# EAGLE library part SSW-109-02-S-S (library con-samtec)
THROUGH-HOLE .025" SQ POST SOCKET Source: Samtec SSW.pdf
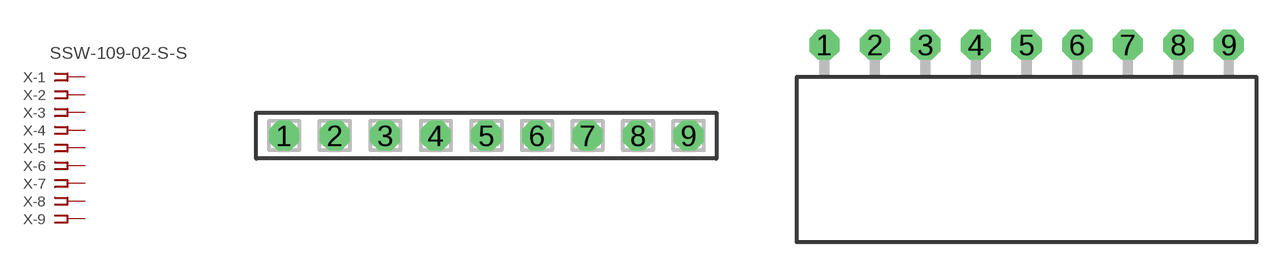
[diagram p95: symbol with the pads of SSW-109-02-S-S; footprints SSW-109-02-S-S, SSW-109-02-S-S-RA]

Designator prefix X; gates -1=FPINV -2=FPIN -3=FPIN -4=FPIN -5=FPIN -6=FPIN -7=FPIN -8=FPIN -9=FPIN

## SSW-109-02-S-S (MPN: SSW-109-02-S-S; OC_FARNELL: unknown; OC_NEWARK: 11P9465)  [SSW-109-02-S-S]
1  -1:1  pas
2  -2:1  pas
3  -3:1  pas
4  -4:1  pas
5  -5:1  pas
6  -6:1  pas
7  -7:1  pas
8  -8:1  pas
9  -9:1  pas

## SSW-109-02-S-S-RA (MPN: SSW-109-02-S-S-RA; OC_FARNELL: unknown; OC_NEWARK: 11P9466)  [SSW-109-02-S-S-RA]
Pads as for SSW-109-02-S-S

## Footprint SSW-109-02-S-S (pad centres in mm)
THROUGH-HOLE .025" SQ POST SOCKET Source: Samtec SSW.pdf
drill 1 pad 1.5 octagon: 1 -10.16,0; 2 -7.62,0; 3 -5.08,0; 4 -2.54,0; 5 0,0; 6 2.54,0; 7 5.08,0; 8 7.62,0; 9 10.16,0

## Footprint SSW-109-02-S-S-RA (pad centres in mm)
THROUGH-HOLE .025" SQ POST SOCKET Source: Samtec SSW.pdf
drill 1 pad 1.5 octagon: 1 -10.16,1.524; 2 -7.62,1.524; 3 -5.08,1.524; 4 -2.54,1.524; 5 0,1.524; 6 2.54,1.524; 7 5.08,1.524; 8 7.62,1.524; 9 10.16,1.524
